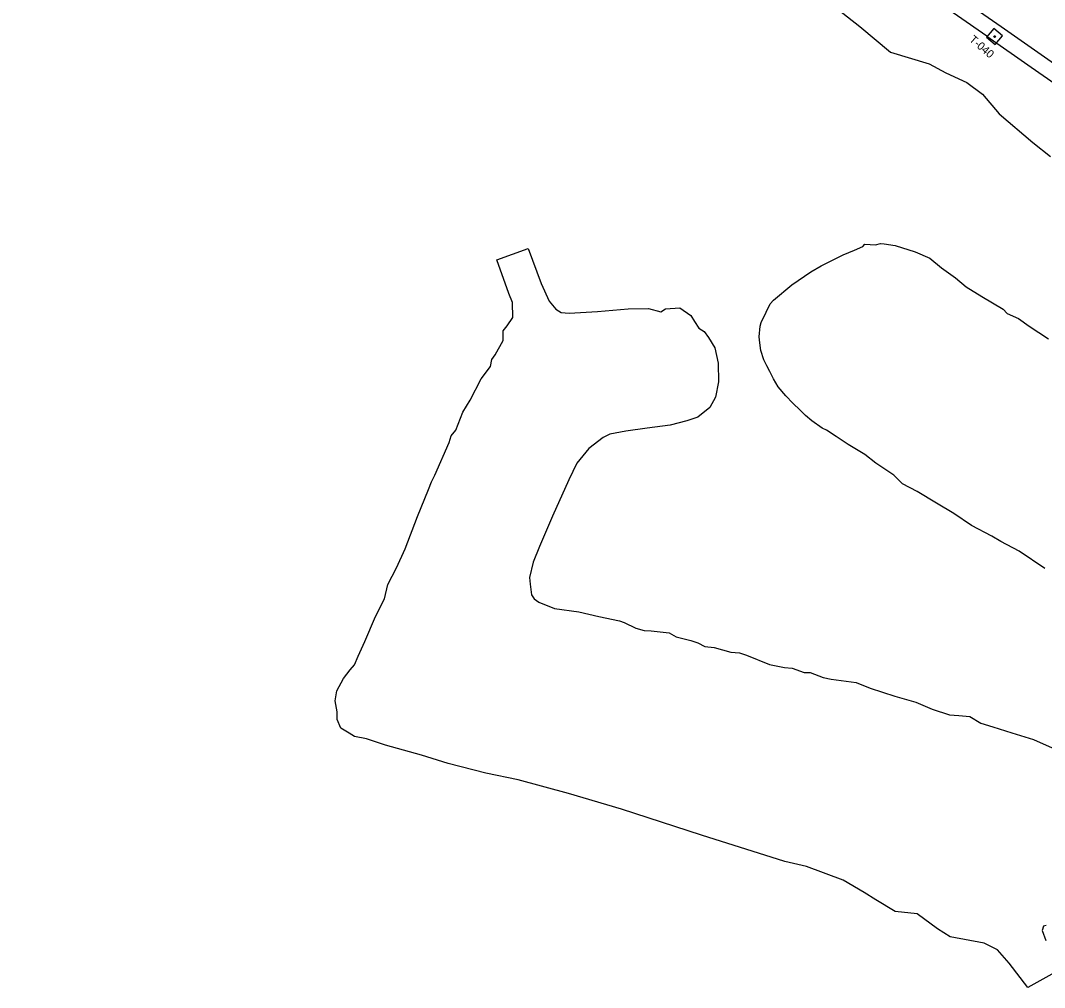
# Model space of a CAD drawing. Extents: x 2076109 to 2080761, y 592812 to 596750.
# Drawn here: x 2078373 to 2079013, y 593620 to 594224 of the extents above; entities that cross this region are included whole.
import ezdxf

# ---------------------------------------------------------------- set-up
doc = ezdxf.new("R2010")
doc.units = 0
for name, color, linetype in [('RD_EX_H2O', 7, 'Continuous'), ('RD_EX_Misc', 7, 'Continuous'), ('RD_EX_Road', 7, 'Continuous'), ('RD_EX_VEG', 7, 'Continuous'), ('RD_HC_Survey', 7, 'Continuous'), ('RD_HC_Survey_txCode', 7, 'Continuous')]:
    doc.layers.add(name, color=color, linetype=linetype)

msp = doc.modelspace()

# ---------------------------------------------------------------- linework, layer by layer
at = {"layer": 'RD_EX_H2O'}
for points in [[(2079023.68, 593631.46), (2079002.9, 593619.93), (2078991.3, 593635.24), (2078984.11, 593643.43), (2078975.74, 593647.65), (2078954.37, 593651.58), (2078946.53, 593656.64), (2078933.8, 593665.89), (2078920.17, 593667.43), (2078907.9, 593674.63), (2078900.78, 593679.25), (2078887.57, 593687.08), (2078864.76, 593695.56), (2078851.11, 593698.58), (2078799.07, 593715.15), (2078749.14, 593731.39), (2078715.86, 593741.1), (2078684.4, 593749.71), (2078664.27, 593753.78), (2078640.74, 593759.92), (2078624.11, 593765.05), (2078601.61, 593771.3), (2078589.73, 593775.18), (2078582.26, 593776.79), (2078578.87, 593778.76), (2078573.75, 593781.83), (2078571.48, 593787.26), (2078571.43, 593792.21), (2078570.17, 593799.01), (2078571.17, 593805.25), (2078575.4, 593812.9), (2078579.58, 593818.44), (2078582.23, 593821.42), (2078584.48, 593826.96), (2078588.78, 593836.13), (2078595.27, 593851.75), (2078600.95, 593862.68), (2078603.11, 593871.68), (2078608.52, 593882.07), (2078613.78, 593894.03), (2078621.49, 593914.14), (2078628.46, 593931.11), (2078630.33, 593935.79), (2078632.39, 593939.97), (2078641.43, 593960.36), (2078642.66, 593964.49), (2078645.51, 593968.14), (2078650.01, 593979.28), (2078654.58, 593986.89), (2078661.35, 594000.06), (2078667.22, 594007.86), (2078668.11, 594012.14), (2078670.16, 594015.08), (2078675.22, 594024.15), (2078675.11, 594030.05), (2078677.58, 594033.27), (2078681.09, 594038.47), (2078680.88, 594047.85), (2078678.66, 594053.38), (2078671.11, 594074.53), (2078690.83, 594081.53), (2078698.93, 594059.68), (2078703.87, 594048.55), (2078707.98, 594043.56), (2078711.37, 594041.49), (2078716.36, 594041.09), (2078734.15, 594042.18), (2078753.27, 594043.87), (2078765.96, 594044.06), (2078773.66, 594042.08), (2078776.6, 594043.8), (2078785.53, 594044.54), (2078792.3, 594039.76), (2078794.68, 594035.98), (2078797.34, 594031.87), (2078800.83, 594029.71), (2078803.36, 594025.88), (2078807.34, 594019.44), (2078809.42, 594009.93), (2078809.69, 593998.19), (2078807.75, 593988.7), (2078804.28, 593982.28), (2078796.81, 593976.24), (2078789.94, 593973.92), (2078779.53, 593971.22), (2078765.18, 593969.4), (2078751.74, 593967.36), (2078741.8, 593965.65), (2078737.55, 593963.48), (2078728.7, 593956.68), (2078721.19, 593947.36), (2078716.13, 593937.14), (2078706, 593914.32), (2078697.8, 593895.36), (2078693.84, 593885.67), (2078691.61, 593875.97), (2078692.04, 593871.83), (2078692.89, 593865.3), (2078694.48, 593862.74), (2078697.32, 593860.68), (2078707.22, 593856.64), (2078722.37, 593854.55), (2078734.88, 593851.63), (2078747.85, 593849), (2078750.66, 593847.87), (2078758.13, 593844.42), (2078763.16, 593842.97), (2078767.54, 593842.72), (2078778.81, 593841.55), (2078783.24, 593838.95), (2078792.44, 593836.78), (2078796.84, 593835.13), (2078801.18, 593832.98), (2078807.05, 593832.29), (2078817.31, 593829.3), (2078822.8, 593828.93), (2078827.08, 593827.57), (2078841.54, 593821.72), (2078850.87, 593819.91), (2078855.72, 593819.44), (2078863.24, 593816.68), (2078866.91, 593816.65), (2078875.1, 593813.6), (2078879.99, 593812.64), (2078895.66, 593810.36), (2078904.42, 593806.91), (2078919.91, 593801.84), (2078933.06, 593798.23), (2078943.23, 593793.85), (2078953.94, 593790.2), (2078959.94, 593789.77), (2078966.69, 593789.14), (2078973.56, 593785.1), (2078981.04, 593782.74), (2078992.93, 593778.98), (2079006.56, 593774.86), (2079022.02, 593768)], [(2079013.68, 593881.64), (2078997.59, 593892.58), (2078986.21, 593898.46), (2078980.49, 593901.79), (2078967.81, 593908.42), (2078956.74, 593915.97), (2078945.96, 593922.54), (2078933.77, 593929.85), (2078924.66, 593934.61), (2078919.18, 593940.05), (2078907.98, 593947.44), (2078901.06, 593952.82), (2078890.73, 593959.18), (2078883.13, 593964.19), (2078877.17, 593968.1), (2078874.49, 593969.38), (2078867.98, 593973.98), (2078863.96, 593977.25), (2078860.62, 593980.57), (2078856.21, 593984.9), (2078851.68, 593989.62), (2078847.04, 593995.07), (2078844.11, 594000.17), (2078841.83, 594004.71), (2078839.81, 594008.28), (2078838.04, 594011.92), (2078836.15, 594017.88), (2078835.58, 594022.71), (2078835.1, 594026.35), (2078835.63, 594033), (2078836.3, 594035.28), (2078839.38, 594041.68), (2078842.06, 594046.95), (2078844.11, 594049.34), (2078855.45, 594058.81), (2078867.4, 594066.93), (2078873.86, 594070.8), (2078887.69, 594077.58), (2078894.67, 594080.55), (2078899.86, 594082.84), (2078901.23, 594084.33), (2078904.44, 594083.98), (2078907.77, 594083.89), (2078910.95, 594084.58), (2078913.24, 594084.56), (2078920.08, 594083.4), (2078932.55, 594079.54), (2078941.66, 594075.42), (2078949.07, 594069.53), (2078957.69, 594063.33), (2078964.43, 594057.64), (2078974.23, 594051.64), (2078987.52, 594043.57), (2078990.15, 594041.04), (2078997.06, 594037.79), (2079003.92, 594033.11), (2079015.91, 594025.14)], [(2079014.43, 593658.77), (2079012.83, 593658.2), (2079012.04, 593655.56), (2079014.21, 593649.37)]]:
    msp.add_lwpolyline(points, dxfattribs=at)
at = {"layer": 'RD_EX_Misc'}
for points in [[(2078384.22, 594665.44), (2078412.71, 594641.87), (2078439.7, 594619.98), (2078465.41, 594599.28), (2078499.3, 594572.31), (2078534.08, 594545.05), (2078572.27, 594515.47), (2078606.85, 594489.18), (2078640.01, 594464.5), (2078673.26, 594440.06), (2078715.65, 594409.47), (2078759.09, 594378.71), (2078798.64, 594350.77), (2078831.82, 594327.55), (2078876.03, 594296.78), (2078911.79, 594271.95), (2078953.79, 594242.84), (2078986.27, 594220.14)], [(2078384.22, 594665.44), (2078412.71, 594641.87), (2078439.7, 594619.98), (2078465.41, 594599.28), (2078499.3, 594572.31), (2078534.08, 594545.05), (2078572.27, 594515.47), (2078606.85, 594489.18), (2078640.01, 594464.5), (2078673.26, 594440.06), (2078715.65, 594409.47), (2078759.09, 594378.71), (2078798.64, 594350.77), (2078831.82, 594327.55), (2078876.03, 594296.78), (2078911.79, 594271.95), (2078953.79, 594242.84), (2078986.27, 594220.14)], [(2078986.27, 594220.14), (2079017.62, 594198.38), (2079053.93, 594172.93), (2079083.86, 594151.83), (2079123.29, 594124.21), (2079172.53, 594089.42), (2079218.8, 594056.49), (2079259.72, 594026.99), (2079297.4, 593999.11), (2079338.75, 593968.09), (2079370.51, 593943.72), (2079406.26, 593915.75), (2079435.34, 593892.84), (2079462.39, 593871.13), (2079490.54, 593848.1), (2079514.75, 593828.45), (2079543.29, 593804.54), (2079566.57, 593785.04), (2079590.1, 593765.16)], [(2078986.27, 594220.14), (2079017.62, 594198.38), (2079053.93, 594172.93), (2079083.86, 594151.83), (2079123.29, 594124.21), (2079172.53, 594089.42), (2079218.8, 594056.49), (2079259.72, 594026.99), (2079297.4, 593999.11), (2079338.75, 593968.09), (2079370.51, 593943.72), (2079406.26, 593915.75), (2079435.34, 593892.84), (2079462.39, 593871.13), (2079490.54, 593848.1), (2079514.75, 593828.45), (2079543.29, 593804.54), (2079566.57, 593785.04), (2079590.1, 593765.16)]]:
    msp.add_lwpolyline(points, dxfattribs=at)
at = {"layer": 'RD_EX_Road'}
for points in [[(2078977.34, 594214.19), (2078959.11, 594226.84), (2078925.13, 594250.42), (2078896.3, 594270.44), (2078872.84, 594286.82), (2078849.12, 594303.34), (2078823.04, 594321.78), (2078796.47, 594340.14), (2078768.74, 594359.44), (2078746.51, 594374.99), (2078718.8, 594394.87), (2078693.36, 594413.27), (2078672.13, 594428.44), (2078644.86, 594448.4), (2078620.36, 594466.36), (2078594.73, 594485.66), (2078571.44, 594503.37), (2078544.9, 594523.86), (2078516.99, 594545.43), (2078491.86, 594565.09), (2078457.22, 594592.46), (2078432.68, 594612.07), (2078397.93, 594640.6), (2078373.49, 594660.86)], [(2078977.34, 594214.19), (2078959.11, 594226.84), (2078925.13, 594250.42), (2078896.3, 594270.44), (2078872.84, 594286.82), (2078849.12, 594303.34), (2078823.04, 594321.78), (2078796.47, 594340.14), (2078768.74, 594359.44), (2078746.51, 594374.99), (2078718.8, 594394.87), (2078693.36, 594413.27), (2078672.13, 594428.44), (2078644.86, 594448.4), (2078620.36, 594466.36), (2078594.73, 594485.66), (2078571.44, 594503.37), (2078544.9, 594523.86), (2078516.99, 594545.43), (2078491.86, 594565.09), (2078457.22, 594592.46), (2078432.68, 594612.07), (2078397.93, 594640.6), (2078373.49, 594660.86)], [(2078977.34, 594214.19), (2079005.03, 594194.88), (2079032.42, 594175.88), (2079060.87, 594156.05), (2079091.29, 594135.14), (2079121.66, 594113.53), (2079150.22, 594093.25), (2079180.58, 594071.46), (2079210.22, 594050.57), (2079243.1, 594026.76), (2079269.97, 594007.04), (2079294, 593989.17), (2079324.8, 593965.9), (2079358.97, 593940.11), (2079393.63, 593913.44), (2079423.61, 593889.81), (2079445.9, 593871.9), (2079474.81, 593848.27), (2079496.87, 593831.11), (2079520.55, 593811.97), (2079536.72, 593798.7), (2079562.77, 593776.14), (2079578.5, 593762.27)], [(2078977.34, 594214.19), (2079005.03, 594194.88), (2079032.42, 594175.88), (2079060.87, 594156.05), (2079091.29, 594135.14), (2079121.66, 594113.53), (2079150.22, 594093.25), (2079180.58, 594071.46), (2079210.22, 594050.57), (2079243.1, 594026.76), (2079269.97, 594007.04), (2079294, 593989.17), (2079324.8, 593965.9), (2079358.97, 593940.11), (2079393.63, 593913.44), (2079423.61, 593889.81), (2079445.9, 593871.9), (2079474.81, 593848.27), (2079496.87, 593831.11), (2079520.55, 593811.97), (2079536.72, 593798.7), (2079562.77, 593776.14), (2079578.5, 593762.27)]]:
    msp.add_lwpolyline(points, dxfattribs=at)
at = {"layer": 'RD_EX_VEG'}
for points in [[(2078869.99, 594242.33), (2078898.02, 594220.2), (2078917.24, 594204.12), (2078941.23, 594196.98)], [(2078869.99, 594242.33), (2078898.02, 594220.2), (2078917.24, 594204.12), (2078941.23, 594196.98)], [(2078941.23, 594196.98), (2078951.8, 594191.24), (2078964.78, 594185.28), (2078974.69, 594177.89), (2078985.06, 594165.68), (2079006.01, 594147.71), (2079017.12, 594138.93)], [(2078941.23, 594196.98), (2078951.8, 594191.24), (2078964.78, 594185.28), (2078974.69, 594177.89), (2078985.06, 594165.68), (2079006.01, 594147.71), (2079017.12, 594138.93)]]:
    msp.add_lwpolyline(points, dxfattribs=at)
at = {"layer": 'RD_HC_Survey'}
msp.add_lwpolyline([(2078987.19, 594214.3), (2078981.84, 594218.93), (2078977.21, 594213.58), (2078982.56, 594208.95)], close=True, dxfattribs=at)
msp.add_lwpolyline([(2078987.19, 594214.3), (2078981.84, 594218.93), (2078977.21, 594213.58), (2078982.56, 594208.95)], close=True, dxfattribs=at)
msp.add_circle((2078982.2, 594213.94), 0.5, dxfattribs=at)
msp.add_circle((2078982.2, 594213.94), 0.5, dxfattribs=at)

# ---------------------------------------------------------------- texts
at = {"layer": 'RD_HC_Survey_txCode'}
msp.add_text('T-040', height=5, rotation=319.16753, dxfattribs=at).set_placement((2078965.99, 594211.47))
msp.add_text('T-040', height=5, rotation=319.16753, dxfattribs=at).set_placement((2078965.99, 594211.47))

doc.saveas('drawing.dxf')
